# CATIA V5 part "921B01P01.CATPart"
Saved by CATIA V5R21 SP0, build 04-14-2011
Part number: 921B01P01
Bounding box of the stored display mesh (mm): x -17.1 to 17.1, y -76.2 to 76.2, z -4.4 to 4.4
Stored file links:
  C:\Users\ALI OZGUN\Desktop\alhan\921B01P01.CATPart
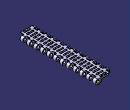
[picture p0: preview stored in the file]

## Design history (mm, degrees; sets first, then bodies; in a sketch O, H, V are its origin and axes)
Body1 (main body)
  Sketch1 on zx-plane, origin (0, 0, 0), H (-1, 0, 0), V (0, 0, 1)
    construction line L1 (-12.7, 0) -> (12.7, 0)
    point P1 (-12.7, 0)
    line L2 (-12.7, 4.4) -> (12.7, 4.4)
    line L3 (12.7, -4.4) -> (-12.7, -4.4)
    arc A1 centre (12.7, 0) radius 4.4 from (12.7, 4.4) to (12.7, -4.4) cw
    arc A2 centre (-12.7, 0) radius 4.4 from (-12.7, -4.4) to (-12.7, 4.4) cw
    distance L1 L2 = 4.4
    length L1 = 25.4
    distance P1 V = 12.7
    coincidence: P1 H
    horizontal: L1 H
    tangency: A1 L2, A2 L2, A1 L3, A2 L3
  Pad1: profile Sketch1, direction (0, 1, 0), length 76.2, mirrored extent
  Sketch2 on face of Pad1 from Sketch1.L2, origin (0, 0, 4.4), H (1, 0, 0), V (0, 1, 0)
    line L1 (-22.3127, -63.5) -> (-9.75, -63.5)
    line L2 (-9.75, -63.5) -> (-9.75, -70.6)
    line L3 (-9.75, -70.6) -> (-22.3127, -70.6)
    line L4 (-22.3127, -70.6) -> (-22.3127, -63.5)
    line L5 (24.6678, -76.95) -> (9.75, -76.95)
    line L6 (9.75, -76.95) -> (9.75, -69.85)
    line L7 (9.75, -69.85) -> (24.6678, -69.85)
    line L8 (24.6678, -69.85) -> (24.6678, -76.95)
    reference projected line E1 (-12.7, -76.2) -> (12.7, -76.2) from edge [start face of Pad1 | face of Pad1 from Sketch1.L2]
    reference projected line E2 (-12.7, -76.2) -> (12.7, -76.2) from edge [start face of Pad1 | face of Pad1 from Sketch1.L2]
    distance L3 E1 = 5.6
    length L4 = 7.1
    distance L7 L5 = 7.1
    distance L5 E2 = 0.75
    distance L2 L6 = 19.5
    distance L2 V = 9.75
    horizontal: L1 H, L3 H, L5 H, L7 H
    vertical: L2 V, L4 V, L6 V, L8 V
  Pocket1: profile Sketch2, direction (0, 0, -1), length 76.2
  RectPattern1: of Pocket1, direction 1 instances 12, spacing 12.7, along axis of face of Pad1 from Sketch1.A2
  Sketch3 on face of Pad1 from Sketch1.L3, origin (0, 0, -4.4), H (1, 0, 0), V (0, -1, 0)
    line L1 (-7, 90.4553) -> (7, 90.4553)
    line L2 (7, 90.4553) -> (7, -88.0088)
    line L3 (7, -88.0088) -> (-7, -88.0088)
    line L4 (-7, -88.0088) -> (-7, 90.4553)
    length L1 = 14
    distance L4 V = 7
    horizontal: L1 H, L3 H
    vertical: L2 V, L4 V
  Pocket2: profile Sketch3, direction (0, 0, 1), length 5.8
  Fillet1: radius 2, on edge [face of Pad1 from Sketch1.L3 | face of Pocket2 from Sketch3.L2]; edge [face of Pad1 from Sketch1.L3 | face of Pocket2 from Sketch3.L4]
  Sketch4 on yz-plane, origin (0, 0, 0), H (0, 1, 0), V (0, 0, 1)
    point P3 (69.85, -4.4)
    point P5 (69.85, -4.4)
    point P7 (57.15, -4.4)
    point P9 (57.15, -4.4)
    point P11 (44.45, -4.4)
    point P13 (44.45, -4.4)
    point P15 (31.75, -4.4)
    point P16 (31.75, -4.4)
    point P18 (19.05, -4.4)
    point P19 (19.05, 1.4)
    point P20 (19.05, -4.4)
    line L1 (-76.2, -4.4) -> (-76.2, 1.4)
    line L2 (-69.85, 1.4) -> (-69.85, -4.4)
    line L3 (-69.85, -4.4) -> (-76.2, -4.4)
    line L4 (-57.15, -4.4) -> (-64.25, -4.4)
    line L5 (-64.25, -4.4) -> (-64.25, 1.4)
    line L6 (-57.15, 1.4) -> (-57.15, -4.4)
    line L7 (-44.45, -4.4) -> (-51.55, -4.4)
    line L8 (-51.55, -4.4) -> (-51.55, 1.4)
    line L9 (-44.45, 1.4) -> (-44.45, -4.4)
    line L10 (-31.75, -4.4) -> (-38.85, -4.4)
    line L11 (-38.85, -4.4) -> (-38.85, 1.4)
    line L12 (-19.05, -4.4) -> (-26.15, -4.4)
    line L13 (-26.15, -4.4) -> (-26.15, 1.4)
    line L14 (-19.05, 1.4) -> (-19.05, -4.4)
    line L15 (-6.35, -4.4) -> (-13.45, -4.4)
    line L16 (-13.45, -4.4) -> (-13.45, 1.4)
    line L17 (-6.35, 1.4) -> (-6.35, -4.4)
    line L18 (6.35, -4.4) -> (-0.75, -4.4)
    line L19 (-0.75, -4.4) -> (-0.75, 1.4)
    line L20 (6.35, 1.4) -> (6.35, -4.4)
    construction line L21 (19.05, -4.4) -> (11.95, -4.4)
    construction line L22 (11.95, -4.4) -> (11.95, 4.4)
    construction line L23 (11.95, 4.4) -> (19.05, 4.4)
    construction line L24 (19.05, 4.4) -> (19.05, -4.4)
    line L25 (19.05, 1.4) -> (19.05, -4.4)
    line L26 (19.05, -4.4) -> (11.95, -4.4)
    line L27 (11.95, -4.4) -> (11.95, 1.4)
    construction line L28 (31.75, -4.4) -> (24.65, -4.4)
    construction line L29 (24.65, -4.4) -> (24.65, 4.4)
    construction line L30 (24.65, 4.4) -> (31.75, 4.4)
    construction line L31 (31.75, 4.4) -> (31.75, -4.4)
    line L32 (31.75, -4.4) -> (24.65, -4.4)
    line L33 (24.65, -4.4) -> (24.65, 1.4)
    line L34 (31.75, 1.4) -> (31.75, -4.4)
    construction line L35 (44.45, -4.4) -> (37.35, -4.4)
    construction line L36 (37.35, -4.4) -> (37.35, 4.4)
    construction line L37 (37.35, 4.4) -> (44.45, 4.4)
    construction line L38 (44.45, 4.4) -> (44.45, -4.4)
    line L39 (44.45, -4.4) -> (37.35, -4.4)
    line L40 (37.35, -4.4) -> (37.35, 1.4)
    line L41 (44.45, 1.4) -> (44.45, -4.4)
    construction line L42 (57.15, -4.4) -> (50.05, -4.4)
    construction line L43 (50.05, -4.4) -> (50.05, 4.4)
    construction line L44 (50.05, 4.4) -> (57.15, 4.4)
    construction line L45 (57.15, 4.4) -> (57.15, -4.4)
    line L46 (57.15, -4.4) -> (50.05, -4.4)
    line L47 (50.05, -4.4) -> (50.05, 1.4)
    line L48 (57.15, 1.4) -> (57.15, -4.4)
    construction line L49 (69.85, -4.4) -> (62.75, -4.4)
    construction line L50 (62.75, -4.4) -> (62.75, 4.4)
    construction line L51 (62.75, 4.4) -> (69.85, 4.4)
    construction line L52 (69.85, 4.4) -> (69.85, -4.4)
    line L53 (69.85, 1.4) -> (69.85, -4.4)
    line L54 (69.85, -4.4) -> (62.75, -4.4)
    line L55 (62.75, -4.4) -> (62.75, 1.4)
    construction line L56 (-76.2, 1.4) -> (76.2, 1.4)
    line L57 (62.75, 1.4) -> (69.85, 1.4)
    line L58 (50.05, 1.4) -> (57.15, 1.4)
    line L59 (37.35, 1.4) -> (44.45, 1.4)
    line L60 (-76.2, 1.4) -> (-69.85, 1.4)
    point P60 (19.05, 1.4)
    line L61 (24.65, 1.4) -> (31.75, 1.4)
    point P61 (24.65, 1.4)
    point P62 (24.65, 1.4)
    point P63 (11.95, 1.4)
    point P64 (6.35, 1.4)
    point P65 (-0.75, 1.4)
    point P66 (-6.35, 1.4)
    point P67 (-13.45, 1.4)
    point P68 (-19.05, 1.4)
    point P69 (-26.15, 1.4)
    point P70 (-38.85, 1.4)
    point P71 (-44.45, 1.4)
    point P72 (-51.55, 1.4)
    point P73 (-57.15, 1.4)
    point P74 (-64.25, 1.4)
    point P75 (-69.85, 1.4)
    line L62 (-64.25, 1.4) -> (-57.15, 1.4)
    line L63 (-51.55, 1.4) -> (-44.45, 1.4)
    line L64 (-38.85, 1.4) -> (-31.75, 1.4)
    line L65 (-26.15, 1.4) -> (-19.05, 1.4)
    line L66 (-13.45, 1.4) -> (-6.35, 1.4)
    line L67 (-0.75, 1.4) -> (6.35, 1.4)
    line L68 (11.95, 1.4) -> (19.05, 1.4)
    line L69 (-31.75, 1.4) -> (-31.75, -4.4)
    coincidence: L24 P60, L29 P61, L60 L61, L56 P62, L56 P63, L56 P64, L56 P65, L56 P66, L56 P67, L56 P68, L56 P69, L56 P70, L56 P71, L56 P72, L56 P73, L56 P74, L56 P75, L60 L62, L62 L63, L63 L64, L64 L65, L65 L66, L66 L67, L67 L68, P3 P5, P7 P9, P11 P13, P15 P16, P18 P20, P19 P60, P61 P62
    vertical: L69 V
  Pocket3: profile Sketch4, direction (1, 0, 0), length 27.8
  Sketch5 on yz-plane, origin (0, 0, 0), H (0, 1, 0), V (0, 0, 1)
    line L1 (-63.5, -4.4) -> (-70.6, -4.4)
    point P1 (-63.5, -4.4)
    point P2 (-70.6, -4.4)
    line L2 (-63.5, 1.4) -> (-63.5, -4.4)
    point P3 (-63.5, 1.4)
    point P4 (-63.5, -4.4)
    line L3 (-70.6, 1.4) -> (-63.5, 1.4)
    point P5 (-70.6, 1.4)
    point P6 (-63.5, 1.4)
    line L4 (-70.6, -4.4) -> (-70.6, 1.4)
    point P7 (-70.6, -4.4)
    point P8 (-70.6, 1.4)
    line L5 (-50.8, 1.4) -> (-50.8, -4.4)
    point P9 (-50.8, 1.4)
    point P10 (-50.8, -4.4)
    line L6 (-57.9, 1.4) -> (-50.8, 1.4)
    point P11 (-57.9, 1.4)
    point P12 (-50.8, 1.4)
    line L7 (-57.9, -4.4) -> (-57.9, 1.4)
    point P13 (-57.9, -4.4)
    point P14 (-57.9, 1.4)
    line L8 (-50.8, -4.4) -> (-57.9, -4.4)
    point P15 (-50.8, -4.4)
    point P16 (-57.9, -4.4)
    line L9 (-38.1, 1.4) -> (-38.1, -4.4)
    point P17 (-38.1, 1.4)
    point P18 (-38.1, -4.4)
    line L10 (-45.2, 1.4) -> (-38.1, 1.4)
    point P19 (-45.2, 1.4)
    point P20 (-38.1, 1.4)
    line L11 (-45.2, -4.4) -> (-45.2, 1.4)
    point P21 (-45.2, -4.4)
    point P22 (-45.2, 1.4)
    line L12 (-38.1, -4.4) -> (-45.2, -4.4)
    point P23 (-38.1, -4.4)
    point P24 (-45.2, -4.4)
    line L13 (-25.4, 1.4) -> (-25.4, -4.4)
    point P25 (-25.4, 1.4)
    point P26 (-25.4, -4.4)
    line L14 (-32.5, 1.4) -> (-25.4, 1.4)
    point P27 (-32.5, 1.4)
    point P28 (-25.4, 1.4)
    line L15 (-32.5, -4.4) -> (-32.5, 1.4)
    point P29 (-32.5, -4.4)
    point P30 (-32.5, 1.4)
    line L16 (-25.4, -4.4) -> (-32.5, -4.4)
    point P31 (-25.4, -4.4)
    point P32 (-32.5, -4.4)
    line L17 (-12.7, 1.4) -> (-12.7, -4.4)
    point P33 (-12.7, 1.4)
    point P34 (-12.7, -4.4)
    line L18 (-19.8, 1.4) -> (-12.7, 1.4)
    point P35 (-19.8, 1.4)
    point P36 (-12.7, 1.4)
    line L19 (-19.8, -4.4) -> (-19.8, 1.4)
    point P37 (-19.8, -4.4)
    point P38 (-19.8, 1.4)
    line L20 (-12.7, -4.4) -> (-19.8, -4.4)
    point P39 (-12.7, -4.4)
    point P40 (-19.8, -4.4)
    line L21 (0, 1.4) -> (0, -4.4)
    point P41 (0, 1.4)
    point P42 (0, -4.4)
    line L22 (-7.1, 1.4) -> (0, 1.4)
    point P43 (-7.1, 1.4)
    point P44 (0, 1.4)
    line L23 (-7.1, -4.4) -> (-7.1, 1.4)
    point P45 (-7.1, -4.4)
    point P46 (-7.1, 1.4)
    line L24 (0, -4.4) -> (-7.1, -4.4)
    point P47 (0, -4.4)
    point P48 (-7.1, -4.4)
    line L25 (12.7, 1.4) -> (12.7, -4.4)
    point P49 (12.7, 1.4)
    point P50 (12.7, -4.4)
    line L26 (5.6, 1.4) -> (12.7, 1.4)
    point P51 (5.6, 1.4)
    point P52 (12.7, 1.4)
    line L27 (5.6, -4.4) -> (5.6, 1.4)
    point P53 (5.6, -4.4)
    point P54 (5.6, 1.4)
    line L28 (12.7, -4.4) -> (5.6, -4.4)
    point P55 (12.7, -4.4)
    point P56 (5.6, -4.4)
    line L29 (18.3, 1.4) -> (25.4, 1.4)
    point P57 (18.3, 1.4)
    point P58 (25.4, 1.4)
    line L30 (18.3, -4.4) -> (18.3, 1.4)
    point P59 (18.3, -4.4)
    point P60 (18.3, 1.4)
    line L31 (25.4, -4.4) -> (18.3, -4.4)
    point P61 (25.4, -4.4)
    point P62 (18.3, -4.4)
    line L32 (25.4, 1.4) -> (25.4, -4.4)
    point P63 (25.4, 1.4)
    point P64 (25.4, -4.4)
    line L33 (38.1, 1.4) -> (38.1, -4.4)
    point P65 (38.1, 1.4)
    point P66 (38.1, -4.4)
    line L34 (31, 1.4) -> (38.1, 1.4)
    point P67 (31, 1.4)
    point P68 (38.1, 1.4)
    line L35 (31, -4.4) -> (31, 1.4)
    point P69 (31, -4.4)
    point P70 (31, 1.4)
    line L36 (38.1, -4.4) -> (31, -4.4)
    point P71 (38.1, -4.4)
    point P72 (31, -4.4)
    line L37 (50.8, 1.4) -> (50.8, -4.4)
    point P73 (50.8, 1.4)
    point P74 (50.8, -4.4)
    line L38 (43.7, 1.4) -> (50.8, 1.4)
    point P75 (43.7, 1.4)
    point P76 (50.8, 1.4)
    line L39 (43.7, -4.4) -> (43.7, 1.4)
    point P77 (43.7, -4.4)
    point P78 (43.7, 1.4)
    line L40 (50.8, -4.4) -> (43.7, -4.4)
    point P79 (50.8, -4.4)
    point P80 (43.7, -4.4)
    line L41 (63.5, 1.4) -> (63.5, -4.4)
    point P81 (63.5, 1.4)
    point P82 (63.5, -4.4)
    line L42 (56.4, 1.4) -> (63.5, 1.4)
    point P83 (56.4, 1.4)
    point P84 (63.5, 1.4)
    line L43 (56.4, -4.4) -> (56.4, 1.4)
    point P85 (56.4, -4.4)
    point P86 (56.4, 1.4)
    line L44 (63.5, -4.4) -> (56.4, -4.4)
    point P87 (63.5, -4.4)
    point P88 (56.4, -4.4)
    line L45 (69.1, 1.4) -> (76.2, 1.4)
    point P89 (69.1, 1.4)
    point P90 (76.2, 1.4)
    line L46 (69.1, -4.4) -> (69.1, 1.4)
    point P91 (69.1, -4.4)
    point P92 (69.1, 1.4)
    line L47 (76.2, -4.4) -> (69.1, -4.4)
    point P93 (76.2, -4.4)
    point P94 (69.1, -4.4)
    line L48 (76.2, 1.4) -> (76.2, -4.4)
    point P95 (76.2, 1.4)
    point P96 (76.2, -4.4)
    distance L4 L2 = 7.1
    coincidence: P96 P93, P95 P90, P94 P91, P92 P89, P88 P85, P87 P82, P86 P83, P84 P81, P80 P77, P79 P74, P78 P75, P76 P73, P72 P69, P71 P66, P70 P67, P68 P65, P64 P61, P63 P58, P62 P59, P60 P57, P56 P53, P55 P50, P54 P51, P52 P49, P48 P45, P47 P42, P46 P43, P44 P41, P40 P37, P39 P34, P38 P35, P36 P33, P32 P29, P31 P26, P30 P27, P28 P25, P24 P21, P23 P18, P22 P19, P20 P17, P16 P13, P15 P10, P14 P11, P12 P9, P8 P5, P7 P2, P6 P3, P4 P1
    fix: L2
  Pocket4: profile Sketch5, direction (-1, 0, 0), length 27.8
  Chamfer1: length 2.5, angle 45, on edge [face of Pocket4 | face of Pocket1 from Sketch2.L6]; edge [face of Pocket4 | face of RectPattern1] (x11); edge [face of RectPattern1 | face of Pocket4] (x11); edge [face of Pocket4 | face of Pocket1 from Sketch2.L2]
  Sketch6 on zx-plane, origin (0, 0, 0), H (-1, 0, 0), V (0, 0, 1)
    circle A1 centre (12.7, 0) radius 2.3
    point P1 (12.7, 0)
    circle A2 centre (-12.7, 0) radius 2.3
    point P2 (-12.7, 0)
    reference projected arc E1 centre (12.7, 0) radius 4.4 from (12.7, -4.4) to (12.7, 4.4) ccw from edge [face of Pocket4 | face of Pad1 from Sketch1.A1]
    reference projected arc E2 centre (-12.7, 0) radius 4.4 from (-12.7, 4.4) to (-12.7, -4.4) ccw from edge [face of Pad1 from Sketch1.A2 | end face of Pad1]
    radius A1 = 2.3
    radius A2 = 2.3
    coincidence: P1 H, P2 H
    concentricity: P1 E1, A2 E2
  Pocket5: profile Sketch6, direction (0, -1, 0), length 97.8, mirrored extent
  Sketch7 on face of Pad1 from Sketch1.L2, origin (0, 0, 4.4), H (1, 0, 0), V (0, 1, 0)
    line L1 (-6.2, -71.4) -> (-6.2, -74.2)
    point P1 (-6.2, -71.4)
    point P2 (-6.2, -74.2)
    line L2 (6.2, -74.2) -> (1, -74.2)
    point P3 (6.2, -74.2)
    point P4 (-6.2, -74.2)
    line L3 (6.2, -74.2) -> (6.2, -71.4)
    point P5 (6.2, -74.2)
    point P6 (6.2, -71.4)
    line L4 (-6.2, -71.4) -> (-1, -71.4)
    point P7 (-6.2, -71.4)
    point P8 (6.2, -71.4)
    line L5 (-6.2, -65.1) -> (-6.2, -68.4)
    point P9 (-6.2, -65.1)
    point P10 (-6.2, -68.4)
    line L6 (6.2, -68.4) -> (1, -68.4)
    point P11 (6.2, -68.4)
    point P12 (-6.2, -68.4)
    line L7 (6.2, -68.4) -> (6.2, -65.1)
    point P13 (6.2, -68.4)
    point P14 (6.2, -65.1)
    line L8 (-6.2, -65.1) -> (-1, -65.1)
    point P15 (-6.2, -65.1)
    point P16 (6.2, -65.1)
    line L9 (1, -65.1) -> (1, -68.4)
    line L10 (-1, -74.2) -> (-1, -71.4)
    point P17 (-1, -68.4)
    line L11 (-1, -68.4) -> (-1, -65.1)
    point P19 (1, -71.4)
    line L12 (1, -71.4) -> (1, -74.2)
    line L13 (-1, -68.4) -> (-6.2, -68.4)
    line L14 (1, -65.1) -> (6.2, -65.1)
    point P23 (-1, -74.2)
    line L15 (-1, -74.2) -> (-6.2, -74.2)
    line L16 (1, -71.4) -> (6.2, -71.4)
    distance L10 L9 = 2
    distance L10 V = 1
    vertical: L9 V, L10 V, L11 V, L12 V
    coincidence: L6 P17, L10 L11, L4 P19, L9 L12, L6 L13, L8 L14, L2 P23, L2 L15, L4 L16, P1 P7, P2 P4, P3 P5, P6 P8, P9 P15, P10 P12, P11 P13, P14 P16
  Pocket6: profile Sketch7, direction (0, 0, -1), length 97.8
  RectPattern2: of Pocket6, direction 1 instances 12, spacing 12.7, along axis of face of Pad1 from Sketch1.A2
Body2
  Solid1: linked copy from another document
  Translate1: Direction yz-plane, Length 25.4, ToTransfor Solid1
